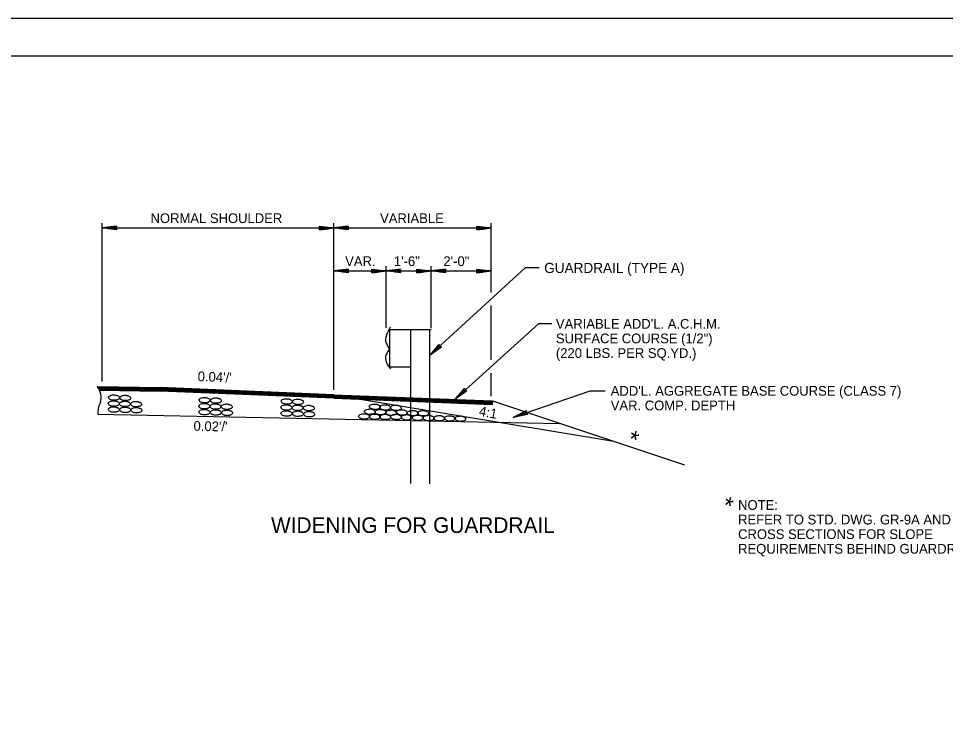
# Model space of a CAD drawing. Extents: x 438659 to 573674, y 10724 to 98600.
# Drawn here: x 448722 to 465846, y 65830 to 79030 of the extents above; entities that cross this region are included whole.
import ezdxf

# ---------------------------------------------------------------- set-up
doc = ezdxf.new("R2010")
doc.units = 0
for name, color, linetype in [('border', 7, 'Continuous'), ('Dimensions', 7, 'Continuous'), ('R_Centerline', 7, 'Continuous'), ('R_Striping', 7, 'Continuous')]:
    doc.layers.add(name, color=color, linetype=linetype)

msp = doc.modelspace()

# ---------------------------------------------------------------- linework, layer by layer
at = {"layer": 'Dimensions'}
for p, q in [((450266, 72316), (450266, 75248)), ((450531, 75192), (450266, 75158)), ((450531, 75179), (450425, 75179)), ((450531, 75186), (450479, 75185)), ((450531, 75192), (450531, 75124)), ((454281, 75192), (454546, 75158)), ((454282, 75123), (454281, 75192)), ((454281, 75185), (454333, 75185)), ((454281, 75178), (454387, 75179)), ((454546, 72165), (454546, 75248)), ((454811, 75192), (454546, 75158)), ((454811, 75179), (454705, 75179)), ((454811, 75186), (454759, 75185)), ((454811, 75192), (454811, 75124)), ((457189, 75192), (457454, 75158)), ((457189, 75123), (457189, 75192)), ((457189, 75185), (457241, 75185)), ((457189, 75178), (457295, 75179)), ((457454, 73965), (457454, 75248)), ((450266, 75158), (454546, 75158)), ((450266, 75158), (450531, 75158)), ((450531, 75124), (450266, 75158)), ((450531, 75165), (450320, 75165)), ((450531, 75151), (450320, 75151)), ((450531, 75172), (450372, 75171)), ((450531, 75144), (450372, 75144)), ((450531, 75137), (450425, 75137)), ((450531, 75130), (450479, 75130)), ((454281, 75172), (454441, 75172)), ((454281, 75165), (454492, 75165)), ((454546, 75158), (454281, 75158)), ((454281, 75144), (454441, 75144)), ((454281, 75130), (454334, 75131)), ((454282, 75123), (454546, 75158)), ((454282, 75151), (454492, 75151)), ((454282, 75137), (454387, 75137)), ((454546, 75158), (457454, 75158)), ((454546, 75158), (454811, 75158)), ((454811, 75124), (454546, 75158)), ((454811, 75165), (454600, 75165)), ((454811, 75151), (454600, 75151)), ((454811, 75172), (454652, 75171)), ((454811, 75144), (454652, 75144)), ((454811, 75137), (454705, 75137)), ((454811, 75130), (454759, 75130)), ((457189, 75172), (457348, 75172)), ((457189, 75165), (457400, 75165)), ((457454, 75158), (457189, 75158)), ((457189, 75123), (457454, 75158)), ((457189, 75151), (457400, 75151)), ((457189, 75144), (457348, 75144)), ((457189, 75137), (457295, 75137)), ((457189, 75130), (457241, 75131)), ((454811, 74398), (454546, 74363)), ((454546, 74363), (455516, 74363)), ((454546, 74363), (454811, 74363)), ((454811, 74329), (454546, 74363)), ((454811, 74370), (454600, 74370)), ((454811, 74357), (454600, 74357)), ((454811, 74377), (454652, 74377)), ((454811, 74350), (454652, 74350)), ((454811, 74384), (454705, 74384)), ((454811, 74343), (454705, 74343)), ((454811, 74391), (454759, 74391)), ((454811, 74336), (454759, 74336)), ((454811, 74398), (454811, 74329)), ((455251, 74398), (455516, 74363)), ((455251, 74329), (455251, 74398)), ((455251, 74391), (455303, 74391)), ((455251, 74384), (455357, 74384)), ((455251, 74377), (455410, 74377)), ((455251, 74370), (455462, 74370)), ((455516, 74363), (455251, 74363)), ((455251, 74329), (455516, 74363)), ((455251, 74357), (455462, 74357)), ((455251, 74350), (455410, 74350)), ((455251, 74343), (455357, 74343)), ((455251, 74336), (455303, 74336)), ((455516, 73310), (455516, 74453)), ((455781, 74398), (455516, 74363)), ((455516, 74363), (456346, 74363)), ((455516, 74363), (455781, 74363)), ((455781, 74329), (455516, 74363)), ((455780, 74370), (455570, 74370)), ((455781, 74357), (455570, 74357)), ((455781, 74377), (455621, 74377)), ((455781, 74350), (455622, 74350)), ((455780, 74384), (455675, 74384)), ((455781, 74343), (455675, 74343)), ((455781, 74391), (455729, 74391)), ((455781, 74336), (455729, 74336)), ((455781, 74398), (455781, 74329)), ((456082, 74398), (456346, 74363)), ((456082, 74329), (456082, 74398)), ((456082, 74391), (456134, 74391)), ((456082, 74384), (456187, 74384)), ((456082, 74377), (456241, 74377)), ((456082, 74370), (456293, 74370)), ((456346, 74363), (456082, 74363)), ((456082, 74329), (456346, 74363)), ((456082, 74357), (456293, 74357)), ((456082, 74350), (456241, 74350)), ((456082, 74343), (456187, 74343)), ((456082, 74336), (456134, 74336)), ((456346, 73302), (456346, 74453)), ((456611, 74398), (456346, 74363)), ((456346, 74363), (457454, 74363)), ((456346, 74363), (456611, 74363)), ((456611, 74329), (456346, 74363)), ((456611, 74370), (456400, 74370)), ((456611, 74357), (456400, 74357)), ((456611, 74377), (456452, 74377)), ((456611, 74350), (456452, 74350)), ((456611, 74384), (456506, 74384)), ((456611, 74343), (456506, 74343)), ((456611, 74391), (456559, 74391)), ((456611, 74336), (456559, 74336)), ((456611, 74398), (456611, 74329)), ((457189, 74398), (457454, 74363)), ((457189, 74329), (457189, 74398)), ((457189, 74391), (457241, 74391)), ((457189, 74384), (457295, 74384)), ((457189, 74377), (457348, 74377)), ((457189, 74370), (457400, 74370)), ((457454, 74363), (457189, 74363)), ((457189, 74329), (457454, 74363)), ((457189, 74357), (457400, 74357)), ((457189, 74350), (457348, 74350)), ((457189, 74343), (457295, 74343)), ((457189, 74336), (457241, 74336)), ((457454, 72717), (457454, 73721)), ((456487, 73004), (456316, 72800)), ((456316, 72800), (456511, 72979)), ((456534, 72954), (456316, 72800)), ((456506, 72984), (456351, 72841)), ((456515, 72974), (456360, 72831)), ((456502, 72989), (456384, 72881)), ((456520, 72969), (456403, 72861)), ((456497, 72994), (456419, 72923)), ((456525, 72964), (456447, 72892)), ((456492, 72999), (456454, 72964)), ((456487, 73004), (456534, 72954)), ((456529, 72959), (456491, 72923)), ((457454, 72049), (457454, 72474)), ((456953, 72189), (456780, 71986)), ((456780, 71986), (456976, 72164)), ((456999, 72138), (456780, 71986)), ((456972, 72169), (456815, 72027)), ((456981, 72159), (456825, 72017)), ((456967, 72174), (456849, 72067)), ((456986, 72154), (456868, 72047)), ((456962, 72179), (456884, 72108)), ((456990, 72149), (456912, 72078)), ((456958, 72184), (456920, 72149)), ((456953, 72189), (456999, 72138)), ((456995, 72143), (456957, 72109)), ((458101, 71774), (457862, 71656)), ((458108, 71755), (457957, 71703)), ((458105, 71761), (458005, 71727)), ((458103, 71768), (458054, 71751)), ((458101, 71774), (458123, 71709)), ((457862, 71656), (458112, 71742)), ((458123, 71709), (457862, 71656)), ((458110, 71748), (457910, 71680)), ((458114, 71736), (457915, 71667)), ((458117, 71729), (457966, 71677)), ((458119, 71722), (458019, 71688)), ((458121, 71716), (458072, 71699))]:
    msp.add_line(p, q, dxfattribs=at)
for points in [[(458338, 74421), (458084, 74421), (456316, 72800)], [(458576, 73388), (458330, 73388), (456780, 71986)], [(459561, 72141), (459275, 72141), (457862, 71656)]]:
    msp.add_lwpolyline(points, dxfattribs=at)
at = {"layer": 'R_Centerline'}
for p, q in [((455572, 73283), (455572, 72590)), ((455572, 73283), (456346, 73283)), ((455960, 73283), (455960, 70430)), ((456316, 73280), (456316, 70429)), ((455572, 72590), (455960, 72590)), ((454544, 72011), (457473, 71894)), ((454545, 72027), (457473, 71910)), ((454546, 72075), (457475, 71959)), ((454546, 72060), (457474, 71943)), ((454546, 72044), (457473, 71927)), ((457475, 71959), (457473, 71894)), ((457475, 71959), (461022, 70779))]:
    msp.add_line(p, q, dxfattribs=at)
msp.add_spline([(455589, 73323), (455517, 73173), (455513, 73026), (455565, 72914), (455517, 72828), (455517, 72670), (455593, 72556)], degree=3, dxfattribs=at)
at = {"layer": 'R_Striping'}
for p, q in [((440478, 78338), (478767, 78338)), ((450177, 72227), (451336, 72205)), ((450189, 72211), (451336, 72187)), ((450198, 72195), (451336, 72171)), ((450207, 72179), (451336, 72155)), ((450217, 72162), (451336, 72141)), ((450217, 72159), (451336, 72138)), ((454545, 72011), (451335, 72141)), ((454546, 72075), (451336, 72205)), ((454546, 72060), (451336, 72187)), ((454546, 72044), (451336, 72171)), ((454546, 72027), (451336, 72155)), ((454545, 72009), (451336, 72138)), ((454546, 72075), (459713, 71215)), ((450187, 71714), (458723, 71543))]:
    msp.add_line(p, q, dxfattribs=at)
for points in [[(479459, 79030), (438659, 79030), (438659, 52630), (479459, 52630)], [(440478, 53322), (440478, 78338), (468896, 78338), (468896, 77152), (473595, 77152), (473595, 76802), (478767, 76802), (478767, 53322)]]:
    msp.add_lwpolyline(points, close=True, dxfattribs=at)
for centre, radius, start, end in [((449916, 72023), 330, 343.9329, 37.9843), ((450573, 71747), 386, 151.4224, 185.1058)]:
    msp.add_arc(centre, radius, start, end, dxfattribs=at)
for points in [[(450479, 71963), (450444, 71959), (450403, 71945), (450381, 71927), (450379, 71916), (450388, 71894), (450400, 71882), (450423, 71869), (450457, 71862), (450476, 71862), (450503, 71864), (450532, 71866), (450555, 71877), (450577, 71896), (450579, 71909), (450574, 71929), (450556, 71941), (450542, 71949), (450516, 71956), (450502, 71960), (450479, 71963)], [(450486, 72074), (450449, 72070), (450409, 72056), (450387, 72039), (450384, 72025), (450393, 72004), (450405, 71993), (450429, 71981), (450463, 71973), (450482, 71973), (450508, 71975), (450536, 71977), (450559, 71987), (450582, 72005), (450586, 72019), (450579, 72039), (450563, 72051), (450547, 72059), (450522, 72066), (450507, 72071), (450486, 72074)], [(450685, 71956), (450650, 71952), (450609, 71939), (450589, 71920), (450585, 71909), (450594, 71888), (450607, 71876), (450630, 71862), (450665, 71856), (450682, 71856), (450709, 71857), (450738, 71860), (450761, 71870), (450782, 71889), (450786, 71902), (450780, 71923), (450764, 71935), (450748, 71943), (450722, 71949), (450708, 71953), (450685, 71956)], [(450693, 72067), (450658, 72063), (450617, 72050), (450597, 72031), (450594, 72019), (450603, 71997), (450614, 71987), (450639, 71973), (450673, 71967), (450690, 71967), (450717, 71967), (450746, 71971), (450769, 71980), (450791, 72000), (450793, 72012), (450786, 72031), (450770, 72044), (450754, 72051), (450732, 72059), (450716, 72063), (450693, 72067)], [(450895, 71952), (450859, 71948), (450819, 71935), (450797, 71916), (450795, 71904), (450804, 71882), (450816, 71872), (450839, 71858), (450873, 71850), (450892, 71850), (450919, 71853), (450947, 71856), (450970, 71865), (450992, 71884), (450995, 71897), (450988, 71916), (450972, 71929), (450956, 71937), (450932, 71944), (450916, 71949), (450895, 71952)], [(452160, 72025), (452124, 72021), (452084, 72008), (452061, 71991), (452058, 71977), (452068, 71956), (452080, 71945), (452104, 71933), (452137, 71925), (452156, 71925), (452183, 71927), (452211, 71929), (452234, 71939), (452256, 71957), (452260, 71971), (452254, 71991), (452238, 72003), (452222, 72011), (452196, 72017), (452181, 72023), (452160, 72025)], [(452367, 72019), (452333, 72015), (452291, 72001), (452271, 71983), (452268, 71971), (452278, 71949), (452288, 71939), (452314, 71925), (452347, 71918), (452365, 71918), (452391, 71918), (452421, 71923), (452444, 71932), (452465, 71952), (452468, 71964), (452461, 71983), (452445, 71996), (452429, 72003), (452406, 72011), (452390, 72015), (452367, 72019)], [(453677, 72001), (453641, 71997), (453601, 71984), (453578, 71967), (453575, 71953), (453585, 71932), (453597, 71921), (453621, 71909), (453654, 71901), (453673, 71901), (453700, 71902), (453728, 71905), (453750, 71914), (453773, 71933), (453777, 71947), (453770, 71967), (453754, 71979), (453738, 71987), (453713, 71993), (453698, 71999), (453677, 72001)], [(453884, 71995), (453849, 71991), (453808, 71977), (453788, 71959), (453785, 71947), (453795, 71925), (453805, 71914), (453831, 71901), (453864, 71894), (453881, 71894), (453908, 71894), (453938, 71898), (453960, 71908), (453982, 71928), (453984, 71940), (453978, 71959), (453962, 71972), (453946, 71979), (453923, 71987), (453907, 71991), (453884, 71995)], [(450479, 71852), (450444, 71848), (450404, 71834), (450384, 71817), (450380, 71803), (450391, 71782), (450401, 71771), (450425, 71759), (450459, 71751), (450478, 71751), (450504, 71753), (450532, 71755), (450555, 71765), (450578, 71783), (450581, 71797), (450574, 71817), (450558, 71829), (450542, 71837), (450518, 71844), (450502, 71849), (450479, 71852)], [(450692, 71846), (450655, 71842), (450615, 71829), (450595, 71811), (450593, 71798), (450602, 71777), (450613, 71766), (450637, 71753), (450670, 71746), (450689, 71746), (450716, 71747), (450744, 71750), (450768, 71759), (450789, 71779), (450792, 71791), (450785, 71811), (450769, 71825), (450753, 71832), (450730, 71840), (450714, 71844), (450692, 71846)], [(450899, 71840), (450864, 71836), (450823, 71822), (450803, 71803), (450800, 71791), (450809, 71771), (450821, 71759), (450844, 71746), (450879, 71738), (450895, 71738), (450922, 71739), (450951, 71743), (450975, 71753), (450996, 71771), (451000, 71786), (450994, 71805), (450978, 71818), (450960, 71825), (450938, 71832), (450922, 71837), (450899, 71840)], [(452153, 71914), (452119, 71910), (452077, 71897), (452056, 71878), (452053, 71868), (452062, 71846), (452074, 71834), (452097, 71821), (452132, 71814), (452151, 71814), (452177, 71816), (452207, 71818), (452230, 71829), (452251, 71848), (452254, 71861), (452248, 71881), (452231, 71893), (452216, 71901), (452191, 71908), (452176, 71912), (452153, 71914)], [(452153, 71803), (452119, 71799), (452079, 71786), (452058, 71769), (452054, 71755), (452065, 71734), (452076, 71723), (452100, 71711), (452133, 71703), (452152, 71703), (452179, 71704), (452207, 71707), (452230, 71717), (452252, 71735), (452255, 71749), (452248, 71769), (452232, 71781), (452216, 71789), (452192, 71795), (452176, 71801), (452153, 71803)], [(452359, 71908), (452325, 71904), (452283, 71890), (452263, 71872), (452259, 71861), (452268, 71840), (452282, 71828), (452305, 71814), (452339, 71807), (452357, 71807), (452383, 71809), (452413, 71811), (452436, 71822), (452457, 71841), (452461, 71854), (452454, 71874), (452438, 71886), (452422, 71894), (452397, 71901), (452382, 71905), (452359, 71908)], [(452366, 71798), (452330, 71794), (452290, 71781), (452270, 71763), (452267, 71750), (452276, 71729), (452287, 71718), (452311, 71704), (452345, 71698), (452363, 71698), (452390, 71699), (452418, 71702), (452442, 71711), (452464, 71731), (452466, 71743), (452460, 71763), (452444, 71777), (452428, 71783), (452405, 71791), (452389, 71795), (452366, 71798)], [(452569, 71904), (452533, 71900), (452493, 71886), (452472, 71868), (452469, 71856), (452478, 71834), (452490, 71824), (452513, 71810), (452548, 71802), (452567, 71802), (452593, 71805), (452622, 71807), (452644, 71817), (452667, 71836), (452670, 71849), (452663, 71868), (452647, 71881), (452631, 71889), (452607, 71896), (452591, 71901), (452569, 71904)], [(452573, 71791), (452539, 71787), (452497, 71774), (452477, 71755), (452474, 71743), (452484, 71723), (452496, 71711), (452519, 71698), (452553, 71690), (452569, 71690), (452596, 71691), (452626, 71695), (452650, 71704), (452671, 71723), (452675, 71738), (452668, 71757), (452652, 71770), (452635, 71777), (452612, 71783), (452596, 71789), (452573, 71791)], [(453670, 71890), (453635, 71886), (453594, 71873), (453572, 71854), (453570, 71844), (453579, 71822), (453591, 71810), (453614, 71797), (453649, 71790), (453667, 71790), (453694, 71791), (453724, 71794), (453746, 71805), (453768, 71824), (453770, 71837), (453765, 71857), (453748, 71869), (453733, 71877), (453708, 71884), (453693, 71888), (453670, 71890)], [(453670, 71779), (453635, 71775), (453595, 71762), (453575, 71745), (453571, 71731), (453582, 71710), (453593, 71699), (453617, 71687), (453650, 71679), (453669, 71679), (453696, 71680), (453724, 71683), (453746, 71692), (453769, 71711), (453772, 71725), (453765, 71745), (453749, 71757), (453733, 71765), (453709, 71771), (453693, 71777), (453670, 71779)], [(453876, 71884), (453841, 71880), (453800, 71866), (453780, 71848), (453776, 71837), (453785, 71816), (453799, 71803), (453821, 71790), (453856, 71783), (453873, 71783), (453900, 71785), (453930, 71787), (453952, 71798), (453974, 71817), (453978, 71830), (453971, 71850), (453955, 71862), (453939, 71870), (453914, 71877), (453899, 71881), (453876, 71884)], [(453883, 71774), (453847, 71770), (453807, 71757), (453786, 71739), (453784, 71726), (453793, 71704), (453804, 71694), (453828, 71680), (453861, 71674), (453880, 71674), (453907, 71675), (453935, 71678), (453959, 71687), (453980, 71707), (453983, 71719), (453976, 71739), (453960, 71753), (453944, 71759), (453922, 71767), (453906, 71771), (453883, 71774)], [(454086, 71880), (454050, 71876), (454010, 71862), (453988, 71844), (453986, 71832), (453995, 71810), (454007, 71799), (454030, 71786), (454065, 71778), (454083, 71778), (454110, 71781), (454138, 71783), (454161, 71793), (454184, 71811), (454186, 71825), (454180, 71844), (454164, 71857), (454148, 71865), (454124, 71872), (454107, 71877), (454086, 71880)], [(454090, 71767), (454055, 71763), (454014, 71750), (453994, 71731), (453991, 71719), (454000, 71699), (454013, 71687), (454035, 71674), (454070, 71666), (454086, 71666), (454113, 71667), (454142, 71671), (454166, 71680), (454188, 71699), (454192, 71714), (454185, 71733), (454169, 71746), (454152, 71753), (454129, 71759), (454113, 71765), (454090, 71767)], [(455216, 71813), (455179, 71807), (455137, 71797), (455116, 71777), (455112, 71765), (455124, 71743), (455136, 71733), (455159, 71721), (455194, 71711), (455211, 71711), (455238, 71714), (455268, 71717), (455291, 71726), (455310, 71745), (455313, 71759), (455306, 71778), (455291, 71790), (455275, 71797), (455251, 71806), (455238, 71811), (455216, 71813)], [(455305, 71901), (455270, 71900), (455227, 71886), (455204, 71866), (455202, 71854), (455212, 71833), (455224, 71824), (455250, 71811), (455284, 71802), (455302, 71802), (455327, 71803), (455357, 71807), (455378, 71816), (455398, 71834), (455401, 71848), (455396, 71868), (455381, 71880), (455366, 71888), (455342, 71898), (455327, 71901), (455305, 71901)], [(455412, 71803), (455375, 71802), (455333, 71787), (455311, 71767), (455309, 71757), (455319, 71734), (455331, 71723), (455355, 71713), (455389, 71704), (455408, 71703), (455433, 71704), (455462, 71710), (455485, 71719), (455505, 71735), (455509, 71750), (455503, 71769), (455486, 71781), (455472, 71791), (455448, 71799), (455433, 71802), (455412, 71803)], [(455497, 71890), (455461, 71888), (455420, 71873), (455398, 71856), (455396, 71844), (455406, 71821), (455417, 71810), (455442, 71799), (455474, 71791), (455492, 71790), (455519, 71790), (455549, 71795), (455571, 71806), (455593, 71822), (455596, 71837), (455589, 71856), (455573, 71870), (455559, 71877), (455533, 71885), (455519, 71888), (455497, 71890)], [(455608, 71793), (455573, 71789), (455531, 71777), (455508, 71757), (455505, 71745), (455516, 71723), (455528, 71714), (455552, 71700), (455585, 71692), (455604, 71692), (455630, 71694), (455660, 71696), (455682, 71706), (455703, 71725), (455706, 71739), (455699, 71758), (455684, 71770), (455668, 71778), (455646, 71786), (455631, 71793), (455608, 71793)], [(455696, 71881), (455660, 71881), (455619, 71866), (455596, 71846), (455593, 71834), (455605, 71813), (455618, 71803), (455640, 71793), (455675, 71782), (455692, 71781), (455719, 71783), (455747, 71789), (455770, 71797), (455791, 71814), (455794, 71828), (455787, 71846), (455773, 71860), (455757, 71870), (455734, 71877), (455719, 71881), (455696, 71881)], [(455803, 71797), (455767, 71793), (455726, 71782), (455704, 71762), (455700, 71750), (455712, 71727), (455726, 71718), (455749, 71706), (455783, 71696), (455799, 71696), (455826, 71699), (455856, 71700), (455880, 71711), (455900, 71730), (455902, 71743), (455896, 71763), (455880, 71775), (455864, 71782), (455841, 71793), (455826, 71797), (455803, 71797)], [(456005, 71783), (455971, 71782), (455926, 71767), (455906, 71747), (455902, 71737), (455914, 71714), (455926, 71704), (455949, 71694), (455984, 71684), (456001, 71683), (456028, 71684), (456056, 71690), (456079, 71699), (456100, 71717), (456104, 71730), (456098, 71749), (456082, 71762), (456067, 71771), (456043, 71779), (456028, 71782), (456005, 71783)], [(456195, 71783), (456161, 71779), (456119, 71767), (456098, 71747), (456094, 71737), (456107, 71714), (456118, 71704), (456142, 71691), (456175, 71683), (456193, 71683), (456219, 71684), (456249, 71687), (456272, 71698), (456292, 71717), (456296, 71730), (456289, 71749), (456273, 71762), (456257, 71767), (456234, 71779), (456218, 71782), (456195, 71783)], [(455108, 71723), (455072, 71722), (455029, 71707), (455009, 71687), (455005, 71675), (455017, 71654), (455029, 71644), (455052, 71634), (455087, 71623), (455104, 71623), (455131, 71624), (455159, 71630), (455182, 71639), (455203, 71656), (455206, 71668), (455199, 71687), (455184, 71700), (455168, 71711), (455144, 71719), (455131, 71722), (455108, 71723)], [(455305, 71717), (455270, 71714), (455227, 71700), (455207, 71682), (455204, 71668), (455215, 71647), (455224, 71638), (455250, 71627), (455283, 71616), (455301, 71616), (455327, 71619), (455358, 71623), (455379, 71630), (455400, 71650), (455404, 71663), (455398, 71682), (455381, 71694), (455365, 71704), (455342, 71713), (455327, 71717), (455305, 71717)], [(455498, 71714), (455462, 71710), (455420, 71698), (455398, 71679), (455396, 71666), (455406, 71644), (455418, 71635), (455442, 71622), (455476, 71614), (455493, 71614), (455520, 71616), (455549, 71618), (455572, 71627), (455592, 71647), (455596, 71659), (455589, 71679), (455573, 71691), (455557, 71699), (455533, 71707), (455520, 71713), (455498, 71714)], [(455699, 71714), (455663, 71710), (455620, 71698), (455599, 71679), (455595, 71666), (455607, 71644), (455619, 71635), (455643, 71620), (455676, 71614), (455694, 71614), (455721, 71615), (455750, 71618), (455773, 71627), (455793, 71647), (455797, 71659), (455790, 71679), (455774, 71692), (455758, 71699), (455735, 71707), (455721, 71711), (455699, 71714)], [(455896, 71706), (455860, 71702), (455818, 71691), (455795, 71671), (455793, 71659), (455803, 71636), (455815, 71627), (455841, 71614), (455873, 71606), (455890, 71606), (455917, 71607), (455948, 71610), (455971, 71620), (455991, 71639), (455993, 71652), (455987, 71672), (455971, 71684), (455956, 71691), (455933, 71699), (455918, 71706), (455896, 71706)], [(456098, 71698), (456062, 71696), (456020, 71680), (456000, 71663), (455996, 71652), (456008, 71630), (456017, 71618), (456043, 71607), (456075, 71599), (456094, 71597), (456120, 71599), (456150, 71604), (456171, 71614), (456194, 71631), (456198, 71644), (456191, 71663), (456175, 71678), (456159, 71686), (456135, 71692), (456120, 71696), (456098, 71698)], [(456298, 71694), (456264, 71691), (456221, 71678), (456201, 71659), (456198, 71646), (456207, 71624), (456218, 71615), (456243, 71604), (456276, 71593), (456294, 71593), (456321, 71596), (456352, 71600), (456373, 71607), (456395, 71627), (456397, 71639), (456391, 71659), (456375, 71671), (456359, 71680), (456336, 71690), (456321, 71692), (456298, 71694)], [(456495, 71691), (456459, 71686), (456416, 71674), (456395, 71655), (456392, 71643), (456403, 71620), (456415, 71612), (456439, 71599), (456472, 71589), (456490, 71589), (456516, 71592), (456546, 71593), (456568, 71604), (456590, 71623), (456593, 71636), (456586, 71655), (456570, 71668), (456555, 71676), (456530, 71684), (456516, 71690), (456495, 71691)], [(456693, 71687), (456655, 71683), (456613, 71672), (456593, 71652), (456589, 71640), (456601, 71619), (456613, 71610), (456637, 71595), (456670, 71587), (456688, 71587), (456714, 71588), (456744, 71592), (456766, 71602), (456787, 71620), (456789, 71634), (456784, 71652), (456768, 71666), (456750, 71672), (456729, 71680), (456716, 71684), (456693, 71687)], [(456885, 71683), (456848, 71678), (456807, 71667), (456785, 71647), (456782, 71635), (456793, 71614), (456805, 71604), (456829, 71592), (456863, 71581), (456880, 71581), (456907, 71585), (456936, 71585), (456959, 71596), (456980, 71615), (456983, 71630), (456976, 71648), (456960, 71660), (456944, 71668), (456923, 71676), (456907, 71680), (456885, 71683)]]:
    msp.add_spline(points, degree=3, dxfattribs=at)

# ---------------------------------------------------------------- texts
at = {"layer": 'border'}
for s, height, p in [('NORMAL SHOULDER', 180, (451160, 75248)), ('VARIABLE', 180, (455401, 75248)), ('VAR.', 180, (454756, 74453)), ('1\'-6"', 180, (455656, 74453)), ('2\'-0"', 180, (456571, 74453)), ('GUARDRAIL (TYPE A) ', 187.5, (458433, 74325)), ("VARIABLE ADD'L. A.C.H.M. ", 180, (458649, 73295)), ('SURFACE COURSE (1/2")', 180, (458649, 73025)), ('(220 LBS. PER SQ.YD.) ', 180, (458649, 72755)), ("ADD'L. AGGREGATE BASE COURSE (CLASS 7)", 180, (459662, 72056)), ('VAR. COMP. DEPTH ', 180, (459662, 71786)), ('NOTE:', 180, (462015, 69946)), (' WIDENING FOR GUARDRAIL ', 288, (453279, 69519)), ('REFER TO STD. DWG. GR-9A AND ', 180, (462015, 69676)), ('CROSS SECTIONS FOR SLOPE ', 180, (462015, 69406)), ('REQUIREMENTS BEHIND GUARDRAIL.', 180, (462015, 69136))]:
    msp.add_text(s, height=height, dxfattribs=at).set_placement(p)
for s, height, rotation, p in [("0.04'/'", 180, 357.7094, (452028, 72326)), ('4:1', 180, 348.9665, (457217, 71690)), ("0.02'/'", 180, 358.8537, (451953, 71408)), ('*', 321, 341.5651, (459952, 71125)), ('*', 321, 341.5651, (461698, 69900))]:
    msp.add_text(s, height=height, rotation=rotation, dxfattribs=at).set_placement(p)

doc.saveas('drawing.dxf')
